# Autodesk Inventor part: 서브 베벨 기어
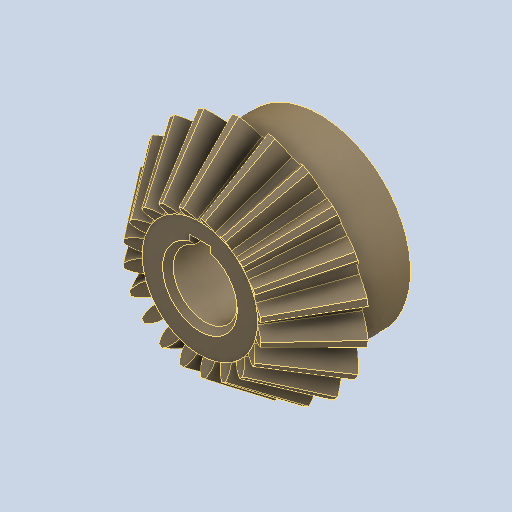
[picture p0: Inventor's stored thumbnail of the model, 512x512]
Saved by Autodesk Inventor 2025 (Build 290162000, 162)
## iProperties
Created: 2024-07
Part Number: 서브 베벨 기어
Material: 강철, 탄소
Document SubType Name: Modeling
Designer: SAMSUNG
Density: 7.87 g/cm^3
Appearance: 기본값
Author: jhkim
Revision Number: 1
Sending System: Autodesk Inventor 2025
Preprocessor: ST-DEVELOPER v20
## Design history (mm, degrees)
node "복구된 형상1"
  node "스케치11"
feature "Solid1"
node "스케치10"
node "솔리드1"
